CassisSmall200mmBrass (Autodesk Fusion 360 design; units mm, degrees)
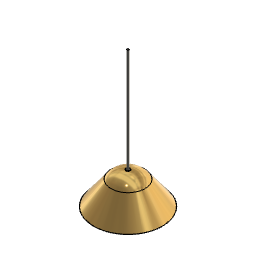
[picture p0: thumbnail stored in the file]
sketch "Sketch1" plane through (0, 0, 0) normal (0, 1, 0) x axis (1, 0, 0)
  line L1 (-5, -92) -> (0, -92)
  line L2 (-49, -69.2459) -> (-100, 0)
  line L3 (0, 0) -> (0, -92)
  line L4 (-100, 0) -> (0, 0)
  arc A1 centre (-2.909, -34.0377) radius 58 clockwise from (-5, -92) to (-49, -69.2459)
  point P1 (0, 0)
  point P4 (-100, 0)
  point P2 (0, -92)
  point P7 (0, 0)
  point P3 (-5, -92)
  point P5 (-49, -69.2459)
  horizontal L1
  horizontal P1 P4
  vertical P1 P2
  coincident P1 P7
  dimension "d1" distance P2 P3 = 5
  dimension "d2" distance P1 L1 = 92
  dimension "d3" distance P1 P4 = 100
  dimension "d4" radius A1 = 58
  dimension "d6" distance P4 P5 = 86
  dimension "d7" distance P1 P5 = 49
revolve "Revolve1" sketch "Sketch1" AlongAngle 360
shell "Shell1" innerThickness 1.5
fillet "Fillet1" radius 0.5
sketch "Sketch2" plane through (0, 0, 0) normal (0, 1, 0) x axis (1, 0, 0)
  line L1 (-32.2676, -70) -> (0, -70)
  point P1 (0, 0)
  horizontal L1
  dimension "d14" distance P1 L1 = 70
work_plane "WorkPlane1" AlongDistance 70
sketch "Sketch4" plane through (0, 0, 70) normal (0, 0, 1) x axis (1, 0, 0)
  circle C1 centre (0, 0) radius 43.7102
  point P1 (0, 0)
  point P2 (0, 0)
  coincident P1 P2
extrude "Extrude2" new body sketch "Sketch4" against normal blind 12 taper -20
sketch "Sketch5" plane through (0, 0, 58) normal (0, 0, -1) x axis (1, 0, 0)
  circle C1 centre (0, 0) radius 39.3425
  circle C2 centre (0, 0) radius 35.3425
  point P1 (0, 0)
  point P3 (0, 0)
  coincident P1 P3
  dimension "d19" distance C1 C2 = 4
extrude "Extrude3" cut sketch "Sketch5" profile of C2 against normal blind 10
extrude "Extrude4" new body of existing geometry blind 20
work_plane "WorkPlane2" AlongDistance -5
split "Split1"
fillet "Fillet2" radius 0.1
fillet "Fillet3" radius 0.4
sketch "Sketch6" plane through (0, 0, 92) normal (0, 0, 1) x axis (-1, 0, 0)
  circle C1 centre (0, 0) radius 5
  circle C2 centre (0, 0) radius 6
  point P1 (0, 0)
  point P3 (0, 0)
  coincident P1 P3
  dimension "d29" diameter C2 = 12
extrude "Extrude5" new body sketch "Sketch6" along normal blind 1.5
extrude "Extrude6" cut of existing geometry blind -1.5
sketch "Sketch7" plane through (0, 0, 70) normal (0, 0, 1) x axis (-1, 0, 0)
  circle C1 centre (0, 0) radius 43.7102
  circle C2 centre (0, 0) radius 3
  point P1 (0, 0)
  point P3 (0, 0)
  coincident P1 P3
  dimension "d34" diameter C2 = 6
extrude "Extrude7" new body sketch "Sketch7" profile of C2 along normal blind 323
fillet "Fillet4" radius 0.2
